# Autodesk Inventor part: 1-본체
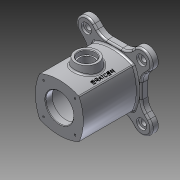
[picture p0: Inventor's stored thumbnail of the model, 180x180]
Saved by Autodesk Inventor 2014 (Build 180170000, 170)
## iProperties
Created: 2016-05
Part Number: 1-본체
Material: 알루미늄 6061
Document SubType Name: Modeling
Designer: Administrator
Mass: 1114.45 g
Surface Area: 865.598 cm^2
Volume: 411.237 cm^3
Density: 2.71 g/cm^3
Appearance: 알루미늄 - 평지
Author: Administrator
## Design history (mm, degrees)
sketch "스케치2"
  geometry: L1 (35.355, -35.355)-(-35.355, 35.355); L2 (0, -60.2)-(0, 60.2) reference; L3 (35.355, 35.355)-(-35.355, -35.355); A1 r 85.579 centre (-42.579, 0) between (35.355, -35.355) and (35.355, 35.355); A2 r 85.579 centre (42.579, 0) between (-35.355, 35.355) and (-35.355, -35.355); A3 r 85.579 centre (0, -42.579) between (35.355, 35.355) and (-35.355, 35.355); A4 r 85.579 centre (0, 42.579) between (-35.355, -35.355) and (35.355, -35.355); 2 further points
  constraints: 8 point on circle, 4 centre point, 4 end point, 2 equal radius, 2 midpoint, 1 coincident
  dimensions: "d3" = 100 distance of L1.start L1.end; "d4" = 45 deg angle of L1 L2; "d5" = 100 distance of L3.start L3.end; "d6" = 45 deg angle of L2 L3; "d7" = 86 dimension on A1 A2; "d8" = 86 dimension on A4 A3
extrude "돌출1" new body sketch "스케치2" stored distance "d9" = 98; taper "d10" = 0 deg
node "작업 평면1"
sketch "스케치3"
  geometry: C1 r 20 at (0, 0); 1 further point
  constraints: 1 centre point, 1 coincident
  dimensions: "d12" = 40 diameter of C1
extrude "돌출2" join sketch "스케치3" stored distance "d13" = 98; taper "d14" = 0 deg
feature "면 기울기1" dims angle "d15" = 10 deg
hole "구멍1" diameter "d18" = 25; stored, may be unused: countersink angle "d22" = 90 deg, drill point angle "d24" = 0 deg; dims "d16" = 10, "d17" = 10, "d19" = 6, "d20" = 30, "d21" = 8, "d23" = 50
chamfer "모따기1" distance "d25" = 1; stored, may be unused: second distance "d26" = 2, angle "d27" = 45 deg
sketch "스케치4" dims "d28" = 70
  geometry: L1 (0, 0)-(49.497, -49.497); L2 (-98, 0)-(98, 0) reference; L3 (49, -49)-(-49, -49); L4 (-49, -49)-(-49, 49); L5 (-49, 49)-(49, 49); L6 (49, 49)-(49, -49); L7 (62.225, -36.77)-(49, -23.544); L8 (36.77, -62.225)-(23.544, -49); L9 (-36.77, -62.225)-(-23.544, -49); L10 (-62.225, -36.77)-(-49, -23.544); L11 (-62.225, 36.77)-(-49, 23.544); L12 (-36.77, 62.225)-(-23.544, 49); L13 (36.77, 62.225)-(23.544, 49); L14 (62.225, 36.77)-(49, 23.544); A1 r 18 centre (49.497, -49.497) between (62.225, -36.77) and (36.77, -62.225); A2 r 18 centre (49.497, 49.497) between (36.77, 62.225) and (62.225, 36.77); A3 r 18 centre (-49.497, 49.497) between (-62.225, 36.77) and (-36.77, 62.225); A4 r 18 centre (-49.497, -49.497) between (-36.77, -62.225) and (-62.225, -36.77); 3 further points
  constraints: 26 end point, 8 parallel, 8 point on circle, 8 point on line, 8 tangent, 4 centre point, 2 coincident, 2 midpoint, 2 perpendicular, 1 collinear, 1 horizontal, 1 horizontal alignment, 1 vertical alignment, 12 other
  dimensions: "d29" = 45 deg angle of L1 L2; "d30" = 18 radius of A1; "d33" = 360 deg dimension on point (0, 0) A1.centre (derived); "d35" = 98 distance of L3.end L4.end; "d36" = 98 distance of L4.end L5.end
extrude "돌출3" join sketch "스케치4" distance "d37" = 12; taper "d38" = 0 deg
fillet "모깎기1" dims "d39" = 25
sketch "스케치5"
  geometry: 2 further points
  constraints: 1 coincident
hole "구멍2" sketch "스케치5" at (0, 0) diameter "d40" = 50; stored, may be unused: countersink angle "d44" = 90 deg, drill point angle "d46" = 0 deg; dims "d41" = 6, "d42" = 30, "d43" = 8, "d45" = 50
sketch "스케치6"
  geometry: C1 r 35 at (0, 0); 1 further point
  constraints: 1 centre point, 1 coincident
  dimensions: "d47" = 70 diameter of C1
extrude "돌출5" cut sketch "스케치6" distance "d52" = 49; taper "d54" = 0 deg; dims "d53" = 37, "d55" = 0
fillet "모깎기2" dims "d56" = 3
fillet "모깎기3" dims "d57" = 3
fillet "모깎기4" dims "d58" = 3
hole "구멍3" diameter "d61" = 10; stored, may be unused: countersink angle "d65" = 90 deg, drill point angle "d67" = 0 deg; dims "d59" = 10, "d60" = 10, "d62" = 6, "d63" = 18, "d64" = 4, "d66" = 50
sketch "스케치7"
  geometry: L1 (0, 0)-(28.284, 28.284); L2 (0, -94.496)-(0, 94.496) reference
  constraints: 2 end point
  dimensions: "d71" = 45 deg angle of L2 L1; "d72" = 40 distance of L1.start L1.end
hole "구멍4" sketch "스케치7" at (28.284, 28.284) diameter "d73" = 3.242; stored, may be unused: countersink angle "d77" = 90 deg, drill point angle "d79" = 118 deg; dims "d74" = 7, "d75" = 18, "d76" = 4, "d78" = 10
sketch "스케치8"
  geometry: L1 (0, 0)-(28.284, 28.284); L2 (0, 94.496)-(0, -94.496) reference
  constraints: 2 end point
  dimensions: "d83" = 45 deg angle of L2 L1; "d84" = 40 distance of L1.start L1.end
hole "구멍5" sketch "스케치8" at (28.284, 28.284) diameter "d85" = 3.242; stored, may be unused: countersink angle "d89" = 90 deg, drill point angle "d91" = 118 deg; dims "d86" = 7, "d87" = 18, "d88" = 4, "d90" = 10
chamfer "모따기2" distance "d95" = 1; stored, may be unused: second distance "d96" = 2, angle "d97" = 45 deg
node "작업 평면2"
sketch "스케치9"
  geometry: 2 further points
  constraints: 1 horizontal alignment, 1 other
  dimensions: "d98" = 29 distance of point (0, 0) point (29, 0)
feature "엠보싱1" sketch "스케치9" dims "d18" = 25, "d99" = 0.5, "d100" = 0
fillet "모깎기5" dims "d101" = 3
fillet "모깎기6" dims "d102" = 3
node "솔리드1"
pattern_circular "원형 패턴1" dims angle "d69" = 360 deg
pattern_circular "원형 패턴2" dims angle "d81" = 360 deg
pattern_circular "원형 패턴3" dims angle "d93" = 360 deg
other parameters: "d11" = 55
